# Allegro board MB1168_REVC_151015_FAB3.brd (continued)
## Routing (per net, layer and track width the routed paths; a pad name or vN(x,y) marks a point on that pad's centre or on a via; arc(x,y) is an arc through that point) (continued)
NETCN6_7: length 27.6
  TOP w0.127: U7.9 14.95,107.23 12.55,109.63 12.55,125.63 11.76,126.42 7.8,126.42 CN6.7
NETCN6_8: length 33.2
  TOP w0.127: U7.7 14.41,108.53 13,109.93 13,125.93 12.19,126.75 9.65,126.75 8.38,128.02 7.24,128.02 6.22,127 6.22,125.22 CN6.8
NETCN7_2: length 10.1
  TOP w0.127: U8.6 97.7,103.55 102.77,108.61 CN7.2
NETCN7_3: length 10.2
  TOP w0.127: U8.10 98.27,106.15 103.5,111.38 CN7.3
NETCN7_6: length 12.6
  TOP w0.127: U8.5 97.82,102.9 102.11,107.19 106.65,107.19 CN7.6
NETCN7_7: length 12.9
  TOP w0.127: U8.9 98.26,105.5 103,110.24 106.43,110.24 CN7.7
NETCN7_8: length 20
  TOP w0.127: CN7.8 108.46,110.97 108.46,109.22 107.82,108.58 106.05,108.58 104.78,109.86 103.25,109.86 97.59,104.2 U8.7
NETCN8_2: length 7.7
  TOP w0.127: R59.1 CN8.2 41.43,102.01 41.43,101.63 SB29.2
NETCN9_4: length 3.4
  TOP w0.127: R74.2 6.73,146.56 5.73,147.56 CN9.4
NETCN10_14: length 96.2
  TOP w0.127: R4.2 32.38,154.94 30.61,154.94 v1(30.35,154.69)
  BOTTOM w0.127: 41.94,88.77 41.94,95.54 45.59,99.19 45.59,104.01 46.86,105.28 46.86,113.92 50.61,117.67 51.75,117.67 54.36,120.27 54.36,131.32 55.12,132.08 57.02,132.08 57.53,132.59 57.53,136.4 52.32,141.6 47.75,141.6 44.32,145.03 35.94,145.03 30.48,150.5 30.48,154.56 v1(30.35,154.69)
NETCN11_2: length 18
  TOP w0.127: 108.01,78.87 105.03,78.87 104.78,79.12 102.25,79.12 U15.4 102.24,80.78 R100.1 102.36,82.17 101.85,82.68 101.85,84.45 101.22,85.09 99.06,85.09 98.04,84.07 CN11.2
NETCN11_4: length 20.3
  TOP w0.127: CN11.4 97.41,82.8 99.31,84.71 101.09,84.71 101.47,84.33 101.47,82.68 100.97,82.17 R99.2 100.94,80.88 U15.5 100.94,78.64 101.35,78.23 104.65,78.23 106.55,76.33 CN12.9
NETCN11_10: length 21.3
  TOP w0.127: CN12.15 102.87,68.71 R111.1 102.74,69.8 99.95,72.59 99.95,74.8 100.94,75.8 U15.1 100.94,77.75 99.69,78.99 CN11.10
NETCN12_11: length 6.5
  TOP w0.127: 108.01,73.79 103.12,73.79 R108.1 102.87,73.53 R109.2
NETCN12_17: length 5.3
  TOP w0.127: R113.2 102.87,66.17 CN12.17
NETCN12_19: length 5.3
  TOP w0.127: R115.2 102.87,63.63 108.01,63.63
NETCN13_2: length 31.5
  TOP w0.127: CN13.2 16.48,71.28 R110.1 17.4,69.34 17.91,68.83 19.3,68.83 22.03,66.1 22.03,64.2 22.73,63.5 37.47,63.5 R119.1 R120.2
NETCN13_7: length 89.9
  TOP w0.127: R144.1 88.77,51.44 84.71,47.37 51.05,47.37 49.78,48.64 32.26,48.64 26.04,54.86 26.04,61.85 25.53,62.36 22.1,62.36 20.32,64.14 18.16,64.14 R114.1 17.65,65.15 17.65,66.29 16,66.29 15.48,65.78 CN13.7
NETCN13_10: length 14.2
  TOP w0.127: R116.2 17.4,63.12 15.49,61.21 6.28,61.21 CN13.10
NETCN14_12: length 3.2
  TOP w0.127: R101.2 39.4,74.14 39.4,70.99
NETCN14_20: length 3.2
  TOP w0.127: R102.2 49.53,71.02 49.56,70.99
NETCN14_22: length 3.2
  TOP w0.127: 52.1,70.99 52.07,71.02 R103.2
NETCN14_24: length 53.5
  TOP w0.127: 54.64,70.99 56.04,69.6 62.87,69.6 63.63,70.36 63.63,75.18 66.67,78.23 80.52,78.23 88.14,85.85 88.14,92.74 R87.1
NETCN14_26: length 63.3
  TOP w0.127: 57.18,70.99 58.2,69.98 62.61,69.98 63.25,70.61 63.25,75.44 66.67,78.87 80.26,78.87 87.12,85.72 87.12,92.58 83.19,96.52 83.19,105.54 R62.1
NETCN14_30: length 58.1
  TOP w0.127: R61.1 82.68,106.55 82.68,96.27 86.61,92.33 86.61,85.94 80.05,79.38 66.55,79.38 62.26,75.09 62.26,70.99
NETCN14_32: length 41.4
  TOP w0.127: 64.8,70.99 64.8,75.72 66.8,77.72 81.03,77.72 88.65,85.34 88.65,91.85 R88.1
NETCN14_34: length 3.2
  TOP w0.127: R104.2 67.31,71.02 67.34,70.99
NETCN14_36: length 3.4
  TOP w0.127: R105.1 69.85,71.02 69.88,70.99
NETCN14_38: length 3.2
  TOP w0.127: R106.2 72.39,71.02 72.42,70.99
NETCN14_40: length 3.2
  TOP w0.127: R107.2 74.93,71.02 74.96,70.99
NETCN16_1: length 3.3
  TOP w0.127: CN16.1 93.85,56.52 R72.2
NETCN16_2: length 8.4
  TOP w0.127: CN16.2 95.89,54.74 95.89,52.96 95.12,52.2 93.6,52.2 93.09,52.7 R75.2
NETCN16_3: length 3.3
  TOP w0.127: CN16.3 93.85,53.98 R135.1
NETCN16_7: length 5
  TOP w0.127: R144.2 92.46,51.44 93.22,50.67 93.22,49.53 CN16.7
NETCN16_8: length 16.1
  TOP w0.508: CN16.8 95.89,47.12 92.58,47.12 91.82,46.35 R145.1 91.06,46.86 91.44,47.24 91.44,47.76 T11.1 ; T11.1 92.4,47.82 92.58,48.01 92.58,48.51 92.33,48.77 T11.2 T11.5 ; T11.1 T11.6
NETCN17_2: length 6.9
  TOP w0.155: CN17.2 102.81,25.9 102.81,25.62 101.41,24.22 101.41,21.4 R193.2
NETCN17_3: length 8.1
  TOP w0.155: CN17.3 103.19,25.9 103.19,25.46 101.79,24.07 101.79,21.4 R194.2 R195.2
NETCN18_1: length 10.5
  TOP w0.508: 20.81,22.64 U27.1 ; U27.1 22.1,23.12 ; U27.1 23.38,22.64 ; U27.1 22.1,22.16 ; CN18.1 11.84,19.3 ; CN18.1 10.64,21.59 ; CN18.1 10.64,17.02 ; CN18.1 9.45,19.3
NETCN19_4: length 3.7
  TOP w0.127: R192.1 72.14,20.01 CN19.4
NETD1_1: length 2.3
  TOP w0.127: D1.1 29.23,133.5 R35.1
NETD1_2: length 2.3
  TOP w0.127: JP3.2 D1.2
NETD2_1: length 2.3
  TOP w0.127: D2.1 JP6.2
NETD2_2: length 26
  TOP w0.127: U7.16 26.27,104.63 v1(26.29,104.65) R63.1 ; D2.2 29.21,125.08 v1(28.07,125.08)
  BOTTOM w0.127: v1(28.07,125.08) 27.18,124.19 27.18,115.32 25.4,113.54 25.4,109.22 26.92,107.7 26.92,105.28 v1(26.29,104.65)
NETD7_2: length 1.4
  TOP w0.127: D7.2 R168.2
NETJP1_3: length 33
  TOP w0.127: v1(61.72,110.11) 51.56,110.11 JP17.3 ; v1(61.72,113.03) 62.61,112.14 69.72,112.14 JP1.3 72.64,105.54 TP18.1
  BOTTOM w0.127: v1(61.72,110.11) v1(61.72,113.03)
NETJP2_1: length 2.5
  TOP w0.127: R29.2 JP2.1
NETJP5_2: length 5.2
  TOP w0.127: JP5.2 R40.1 TP6.1
NETJP8_1: length 4.1
  TOP w0.127: JP8.1 R59.2
NETJP8_2: length 19.5
  TOP w0.127: JP8.2 46.99,109.6 63.25,109.6 63.63,109.22
NETJP9_3: length 11.7
  TOP w0.127: U7.17 24.13,105.28 23.5,104.65 23.5,103.63 23.88,103.25 28.07,103.25 JP9.3
NETJP10_3: length 22.3
  TOP w0.356: U21.5 84.16,42.38 v1(84.71,42.93)
  TOP w0.508: 102.44,49.66 JP10.3 ; JP10.3 103.38,48.72 ; JP10.3 104.32,49.66 ; JP10.3 103.38,50.6 ; 83.77,52.7 R134.1 83.19,52.13
  TOP w0.762: R130.1 51.69,51.56 ; R133.1 75.95,50.04 ; R132.1 66.29,50.04 ; R131.1 58.93,49.91
  BOTTOM w0.508: v1(84.05,49.35) 84.05,44.98 84.71,44.32 v1(84.71,42.93)
NETJP11_4: length 15.3
  TOP w0.508: JP11.4 8.51,44.45 9.53,43.43 12.06,43.43 12.83,44.2 12.83,44.96 15.11,47.24 L5.1 17.66,47.24 19.56,45.34 SB38.2
NETJP12_2: length 3.7
  TOP w0.508: L6.1 103.63,41.02 JP12.2
NETL9_1: length 3.7
  TOP w0.508: L9.1 86.11,29.08 SB40.2
NETL12_1: length 3.2
  TOP w0.127: R142.1 R141.2 L12.1
NETLD1_2: length 3.2
  TOP w0.127: R202.2 LD1.2
NETLD2_2: length 3.2
  TOP w0.127: R201.2 LD2.2
NETLD3_2: length 3.2
  TOP w0.127: R200.2 LD3.2
NETLD4_2: length 3.2
  TOP w0.127: R199.2 LD4.2
NETLD5_1: length 1.5
  TOP w0.127: LD5.1 R153.1
NETLD6_2: length 1.8
  TOP w0.127: R204.2 52.69,13.58 LD6.2
NETLD6_3: length 1.9
  TOP w0.127: LD6.3 50.92,12.06 52.58,12.06 R209.2
NETLD6_4: length 2.2
  TOP w0.127: LD6.4 45.84,12.08 R208.1
NETLD7_2: length 5.3
  TOP w0.127: R210.1 LD7.2
NETLD8_1: length 32.8
  TOP w0.127: U28.1 28.79,25.61 27.94,24.77 26.08,24.77 25.02,23.71 25.02,21.55 22.86,19.39 22.86,17.4 19.94,14.48 16,14.48 14.61,13.08 14.61,12.32 15.37,11.56 15.37,5.46 LD8.1
NETLD8_2: length 5.3
  TOP w0.127: LD8.2 R211.1
NETLD9_1: length 31.1
  TOP w0.127: U28.7 28.14,23.93 27.81,24.26 26.29,24.26 25.53,23.5 25.53,21.34 23.37,19.18 23.37,17.27 20.07,13.97 16.89,13.97 16.38,13.46 16.38,12.32 17.27,11.43 17.27,5.33 LD9.1
NETLD9_2: length 5.3
  TOP w0.127: R212.1 LD9.2
NETLD10_1: length 70.4
  TOP w0.127: R65.2 45.59,41.15 46.35,41.91 46.35,45.34 47.62,46.61 49.28,46.61 49.78,46.1 74.8,46.1 75.44,45.47 87,45.47 89.03,43.43 89.03,38.1 93.09,34.04 100.33,34.04 LD10.1
NETLD10_2: length 75.3
  TOP w0.127: LD10.2 99.22,34.45 93.26,34.45 89.44,38.27 89.44,43.6 87.17,45.88 75.61,45.88 74.97,46.51 50.13,46.51 49.5,47.15 47.4,47.15 45.72,45.47 45.72,42.04 44.96,41.27 44.96,39.37 R68.2 44.45,38.73 43.48,39.71 U29.8
NETLS1_1: length 70.5
  TOP w0.127: R18.2 50.42,153.42 49.4,154.43 38.99,154.43 38.48,154.94 38.48,156.08 ; 37.97,165.61 37.97,166.12 38.35,166.5 86.74,166.5 87.25,165.99 87.25,165.35
NETLS1_2: length 13.1
  TOP w0.127: 54.86,156.46 54.86,154.18 55.63,153.42 59.44,153.42 60.33,152.53 R12.2
NETLS1_3: length 9.5
  TOP w0.127: 71.12,156.34 71.12,153.8 68.71,151.38 R13.2
NETR1_1: length 190.6
  TOP w0.127: R10.1 v1(34.29,149.86) 35.18,150.75 35.18,165.1 R1.1 ; R52.2 v1(74.93,116.08) R53.1 ; R177.1 75.06,30.1 74.3,30.1 v1(73.53,30.86)
  BOTTOM w0.127: v1(73.53,30.86) 73.28,30.86 70.23,33.91 70.23,43.14 75.1,48.01 77.22,48.01 84.58,55.37 84.58,63.45 83.57,64.47 83.57,80.64 87.5,84.58 87.5,90.04 82.8,94.74 82.8,107.31 76.83,113.28 75.31,113.28 74.42,114.17 74.42,115.19 74.93,115.7 v1(74.93,116.08) 74.93,116.59 73.15,118.36 68.93,118.36 67.82,119.48 67.82,133.1 64.9,136.02 61.72,136.02 58.42,139.32 56.13,139.32 49.53,145.92 37.08,145.92 34.29,148.72 v1(34.29,149.86)
NETR2_1: length 188.7
  TOP w0.127: R2.1 34.42,163.32 34.42,151.51 v1(34.29,151.38) R9.1 ; R55.2 v1(74.93,114.55) R56.1 ; R179.1 v1(75.06,28.57)
  BOTTOM w0.127: v1(34.29,151.38) 35.18,150.5 35.18,148.97 37.85,146.3 49.66,146.3 56.28,139.68 58.57,139.68 61.98,136.27 65.41,136.27 68.2,133.48 68.2,119.63 69.09,118.75 73.41,118.75 75.56,116.59 75.56,115.7 74.93,115.06 v1(74.93,114.55) 74.93,114.3 75.44,113.79 76.83,113.79 83.31,107.31 83.31,95 87.88,90.42 87.88,84.33 84.07,80.52 84.07,64.64 84.96,63.75 84.96,55.12 77.34,47.5 75.31,47.5 70.61,42.8 70.61,34.04 73.03,31.62 74.17,31.62 74.93,30.86 74.93,28.7 v1(75.06,28.57)
NETR4_1: length 4.6
  TOP w0.127: 31.62,154.18 31.88,153.92 R6.2 31.75,152.53 U2.3
NETR5_1: length 3.6
  TOP w0.127: R5.1 21.34,152.15 ; 21.72,151.76 22.23,151.26 U2.7
NETR9_2: length 2.8
  TOP w0.127: 31.62,151.38 31.5,151.26 U2.2
NETR10_2: length 2.8
  TOP w0.127: 31.62,149.86 31.5,149.99 U2.1
NETR12_1: length 2
  TOP w0.127: SB8.2 R12.1
NETR13_1: length 2
  TOP w0.127: SB11.1 68.7,146.3 R13.1
NETR18_1: length 1.7
  TOP w0.127: SB6.2 R18.1
NETR20_1: length 7.7
  TOP w0.127: R22.1 R21.1 R20.1 109.35,141.35 108.28,140.28 U4.3
NETR23_1: length 1.5
  TOP w0.127: R24.2 R23.1
NETR24_1: length 3.1
  TOP w0.127: U4.5 100.5,140.93 R24.1
NETR32_1: length 5.7
  TOP w0.127: R32.1 108.93,138.98 U4.1 105.7,138.98 105.16,138.43 R34.2
NETR32_2: length 4.2
  TOP w0.127: R33.1 R32.2 108.89,139.63 U4.2
NETR35_2: length 30.1
  TOP w0.127: R35.2 v1(27.18,133.48) ; U7.20 25.82,107.23 26.04,107.44 v1(26.29,107.44)
  BOTTOM w0.127: v1(26.29,107.44) 26.16,107.44 24.89,108.71 24.89,113.67 26.54,115.32 26.54,132.84 v1(27.18,133.48)
NETR36_2: length 4.7
  TOP w0.127: R36.2 32.77,130.94 SW1.2
NETR37_2: length 1.9
  TOP w0.127: R37.2 40.01,131.06 SB17.1
NETR57_1: length 3.7
  TOP w0.254: U6.5 32.64,112.65 R58.2 R57.1
NETR61_2: length 2.7
  TOP w0.127: U8.16 86.72,108.1 R61.2
NETR62_2: length 2.7
  TOP w0.127: U8.17 86.62,107.45 R62.2
NETR66_1: length 1.8
  TOP w0.127: U29.5 R66.1
NETR67_2: length 6.2
  TOP w0.127: R67.2 55.37,100.71 U9.3 U9.4
NETR83_1: length 3.5
  TOP w0.127: U12.2 92.82,95.63 92.18,96.27 R83.1 91.54,95.12 R87.2
NETR88_2: length 3.9
  TOP w0.127: R89.1 91.8,92.46 R88.2 92.51,94.18 92.51,94.89 92.74,95.13 U12.3
NETR90_2: length 2.2
  TOP w0.508: R90.2 6.71,89.69 U14.1
NETR91_1: length 2.4
  TOP w0.127: U14.5 5.24,85.89 R91.1
NETR93_1: length 3.8
  TOP w0.127: U13.2 18.17,83.44 R94.1 16.89,83.19 R93.1
NETR95_1: length 3.8
  TOP w0.127: R96.1 20.07,83.19 R95.1 18.66,83.57 U13.3
NETR101_1: length 20.9
  TOP w0.127: R117.1 35.56,60.83 v1(35.81,60.83) R118.1 36.18,59.68 U18.5 ; v1(38.35,75.69) R101.1
  BOTTOM w0.127: v1(35.81,60.83) 35.81,65.28 38.35,67.82 v1(38.35,75.69)
NETR116_1: length 71.2
  TOP w0.127: v1(20.32,63.37) R116.1 ; U25.15 61.88,32.48 61.59,32.77 58.04,32.77 v1(56.01,30.73)
  BOTTOM w0.127: v1(56.01,30.73) 55.5,30.23 48.39,30.23 47.37,31.24 47.37,35.43 49.78,37.85 49.78,44.2 41.4,52.58 35.69,52.58 34.8,53.47 34.16,53.47 32.56,55.07 32.56,56.46 32.08,56.95 30.68,56.95 28.96,58.67 26.54,58.67 25.65,59.56 23.37,59.56 20.32,62.61 v1(20.32,63.37)
NETR119_2: length 2.1
  TOP w0.127: R119.2 38.74,59.57 U19.7
NETR121_1: length 10.4
  TOP w0.127: R122.1 R121.1 43.18,60.83 43.18,59.44 39.75,56.01 38.99,56.01 38.74,55.75 U19.2
NETR129_1: length 4
  TOP w0.254: R129.1 R143.2 23.75,52.07 24.51,51.31 U20.5
NETR136_1: length 3
  TOP w0.127: R137.1 R136.1 30.74,53.97 U17.2
NETR138_1: length 1.7
  TOP w0.127: R138.1 35.18,54.61 U18.2
NETR139_1: length 3.1
  TOP w0.127: U19.3 39.24,54.11 R139.1 R140.2
NETR142_2: length 8.1
  TOP w0.127: R142.2 43.31,53.09 v1(43.18,53.09) ; U19.6 39.24,58.27 v1(39.24,57.15)
  BOTTOM w0.127: v1(43.18,53.09) 43.05,53.09 39.24,56.9 v1(39.24,57.15)
NETR147_1: length 2.2
  TOP w0.457: R147.1 23.56,45.78 U20.1
NETR149_1: length 4.6
  TOP w0.508: U22.5 98.42,41.27 R154.2 R149.1
NETR149_2: length 109.1
  TOP w0.127: R149.2 v1(99.95,44.96)
  BOTTOM w0.127: RV1.1 43.05,8.26 46.74,11.94 64.26,11.94 65.02,11.18 97.16,11.18 103.25,17.27 103.25,19.68 99.69,23.24 99.69,44.7 v1(99.95,44.96)
NETR157_1: length 4.7
  TOP w0.127: U25.2 69.56,35.9 69.98,36.32 69.98,37.21 69.6,37.59 R157.1 70.61,38.1 R158.2
NETR159_1: length 5.3
  TOP w0.356: U21.1 86.53,40.43 86.49,40.39 ; 86.49,40.39 R159.1 ; 86.49,40.39 86.49,40.77 86.8,41.08 U21.2
NETR159_2: length 4.4
  TOP w0.127: U23.5 84.29,35.27 84.96,35.94 R163.1 R159.2
NETR162_1: length 5.7
  TOP w0.356: R162.1 84.58,39.75 84.58,41.15 ; U21.7 84.51,41.08 84.58,41.15 ; 84.58,41.15 84.58,41.53 84.38,41.73 U21.6
NETR163_2: length 6.6
  TOP w0.127: 86.49,33.96 R163.2 ; 86.49,33.96 U23.2 ; 86.49,33.96 86.49,33.53 86.7,33.31 U23.1
NETR166_2: length 3.1
  TOP w0.127: U25.46 73.12,32.48 R166.2
NETR169_2: length 2.7
  TOP w0.127: R169.2 74.15,31.98 U25.45
NETR171_1: length 2.3
  TOP w0.127: R171.1 60.82,31.48 U25.17
NETR171_2: length 4.3
  TOP w0.127: U25.16 61.74,31.98 61.34,32.38 59.94,32.38 R171.2
NETR172_1: length 2.5
  TOP w0.127: R172.1 50.28,31.48 U24.20
NETR174_1: length 3.2
  TOP w0.127: U25.44 73.8,31.48 R174.1
NETR175_1: length 2.6
  TOP w0.127: R175.1 36.69,29.98 U24.44
NETR176_1: length 4.3
  TOP w0.127: U25.21 61.96,29.48 61.34,30.1 59.82,30.1 R176.1
NETR176_2: length 2.5
  TOP w0.127: U25.22 61.85,28.98 61.37,29.46 R176.2
NETR177_2: length 3.3
  TOP w0.127: U25.43 72.65,30.98 R177.2
NETR178_2: length 3.1
  TOP w0.127: U26.2 54.61,28.45 R178.2 R181.2
NETR179_2: length 4.3
  TOP w0.127: R179.2 73.66,28.45 73.66,29.34 72.51,30.48 U25.42
NETR180_1: length 5.2
  TOP w0.127: U25.41 72.38,29.98 73.41,28.96 73.41,27.18 R180.1
NETR182_2: length 3.9
  TOP w0.127: R182.2 39.5,24.33 39.9,24.74 40.67,24.74 41.18,25.26 U24.2
NETR183_2: length 2.9
  TOP w0.127: U24.3 41.68,24.79 R183.2
NETR187_1: length 6.9
  TOP w0.127: U24.12 46.18,25.93 46.48,25.63 47.45,25.63 48.56,24.51 49.33,24.51 49.89,23.95 49.89,23.01 R187.1
NETR188_1: length 4.6
  TOP w0.127: U25.28 66.06,24.79 65.41,24.13 65.41,22.99 R188.1
NETR188_2: length 2.8
  TOP w0.127: U25.27 65.56,24.67 R188.2
NETR189_1: length 4.3
  TOP w0.127: U25.30 67.06,23.12 R189.1
NETR189_2: length 2.6
  TOP w0.127: U25.29 66.56,24.14 R189.2
NETR190_1: length 4.5
  TOP w0.127: R190.1 68.45,22.99 68.45,24.38 68.06,24.78 U25.32
NETR190_2: length 2.6
  TOP w0.127: U25.31 67.56,24.13 R190.2
NETR191_1: length 10.9
  TOP w0.127: U25.26 65.06,25.56 64.01,24.51 64.01,21.72 64.26,21.46 68.45,21.46 R191.1
NETR191_2: length 2.8
  TOP w0.127: R191.2 68.56,24.66 U25.33
NETR195_1: length 2.5
  TOP w0.127: T14.2 103.5,17.63 R195.1
NETR196_1: length 11.8
  TOP w0.127: R196.1 R197.2 v1(27.56,18.29) ; v1(28.14,25.84) U28.2
  BOTTOM w0.127: v1(28.14,25.84) 28.14,19.88 27.56,19.3 v1(27.56,18.29)
NETR197_1: length 4.1
  TOP w0.127: U28.6 27.49,19.74 R197.1 R198.2
NETR205_2: length 4.3
  TOP w0.127: T14.1 103.5,15.39 R207.2 R206.1 R205.2
NETSB33_2: length 7.3
  TOP w0.127: SB33.2 55.37,102.36 U11.4 55.69,103.06 56.52,103.89 57.4,103.89 57.59,104.07 U11.1
NETTP26_1: length 10
  TOP w0.127: U25.11 65.06,35.78 64.64,36.2 61.21,36.2 60.71,35.69 57.91,35.69 TP26.1
NETTP27_1: length 7.5
  TOP w0.127: TP27.1 64.64,36.83 65.56,35.91 U25.10
NETTP28_1: length 6.6
  TOP w0.127: TP28.1 52.17,32.36 49.89,32.36 49.51,31.98 U24.21
NETTP29_1: length 8.5
  TOP w0.127: U25.12 57.94,35.08 TP29.1
NETTP31_1: length 23.3
  TOP w0.127: TP31.1 65.53,13.84 65.53,19.3 63.63,21.21 63.63,26.92 65.66,28.96 65.66,31.5 64.17,32.98 U25.14
NETU1_2: length 10.4
  TOP w0.127: U3.3 107.77,147.26 108.2,147.7 108.2,149.35 110.87,152.02 110.87,153.67 110.49,154.05 U1.2
NETU1_4: length 14.7
  TOP w0.127: U1.4 107.7,156.59 107.19,156.08 107.19,151.26 106.81,150.88 102.81,150.88 102.41,150.48 U3.5
NETU7_13: length 32.1
  TOP w0.279: U7.13 16.49,104.63 v1(16.26,104.39) ; U13.7 18.17,89.4 17.78,89.79 v1(17.14,89.79)
  TOP w0.508: v1(17.14,89.79) 10.03,89.79 8.51,88.27 5.84,88.27 5.36,87.78 U14.3
  BOTTOM w0.381: v1(17.14,89.79) 16.26,90.68 v1(16.26,104.39)
NETU8_13: length 15.6
  TOP w0.127: v1(94.36,108.08) 95.86,108.08 U8.13 ; U12.7 95.13,95.63 v1(94.87,95.89)
  BOTTOM w0.127: v1(94.36,108.08) 94.49,108.08 95,107.57 95,96.01 v1(94.87,95.89)
NETU24_13: length 2.5
  TOP w0.127: U26.7 49.38,28.45 48.91,27.98 U24.13
OSC_IN: length 11.4
  TOP w0.203: X3.2 40.64,18.29 42.62,20.27 42.62,23.04 C112.2 42.68,24.27 U24.5
OSC_OUT: length 11.3
  TOP w0.203: X3.1 45.15,18.35 43,20.5 43,23.06 C113.2 43.18,24 U24.6
PA0: length 50.8
  TOP w0.127: CN5.5 87.12,137.92 71.63,137.92 65.96,132.25 U5.23 ; R38.2 v1(106.68,133.22)
  BOTTOM w0.127: CN5.5 91.44,142.24 96.52,142.24 R38.2 v1(106.68,133.22)
PA1: length 14
  TOP w0.127: SB12.2 SB11.2 68.71,142.74 68.71,135.51 65.95,132.75 U5.24
PA2: length 12.9
  TOP w0.127: U5.25 65.82,133.25 67.18,134.62 67.18,142.49 SB10.2 SB9.2
PA4: length 39.6
  TOP w0.127: U5.29 61.65,137.72 v1(61.85,137.92) ; CN5.6 91.19,142.49 89.41,142.49 87.5,144.4 84.2,144.4 JP2.2
  BOTTOM w0.127: JP2.2 80.9,144.91 70.87,144.91 64.77,138.81 62.74,138.81 v1(61.85,137.92)
PA5: length 42.5
  TOP w0.127: v1(80.14,148.72) R8.2 ; U5.30 61.15,137.86 v1(61.09,137.92)
  BOTTOM w0.127: v1(61.09,137.92) 63.37,140.21 65.15,140.21 73.66,148.72 v1(80.14,148.72) 86.49,148.72 87.88,147.32 87.88,144.53 88.9,143.51 CN5.3
PA7: length 34
  TOP w0.127: v1(62.23,133.35) 61.72,132.84 60.96,132.84 60.15,133.65 U5.32
  BOTTOM w0.127: JP1.2 74.04,110.36 73.03,110.36 66.42,116.97 66.42,128.91 62.23,133.1 v1(62.23,133.35)
PA11: length 58
  TOP w0.155: R69.1 12.36,149.1 12.81,148.65 14.81,148.65 18.57,144.89 18.57,130.62 19.46,129.73 23.05,129.73 CN4.14 25.21,129.73 26.99,129.73 28.83,127.89 37.97,127.89 39.12,126.75 45.62,126.75 46.23,126.14 46.23,125.22 47.76,123.69 48.29,123.69 48.34,123.75 U5.70
PA12: length 58
  TOP w0.155: U5.71 48.34,123.25 48.29,123.31 47.6,123.31 45.85,125.06 45.85,125.98 45.46,126.36 38.96,126.36 37.82,127.51 28.67,127.51 26.83,129.35 25.21,129.35 CN4.16 23.05,129.35 19.3,129.35 18.19,130.46 18.19,144.74 14.65,148.27 12.81,148.27 12.36,147.83 R70.1
PA13: length 31.6
  TOP w0.127: U5.72 46.92,122.75 45.34,124.33 45.34,124.71 R45.2 44.07,124.71 38.61,124.71 37.67,123.77 27.99,123.77 25.02,126.74 23.12,126.74 CN4.15
PA14: length 33.7
  TOP w0.127: U5.76 51.15,118.71 50.04,117.6 45.72,117.6 R51.2 43.05,120.27 39.24,120.27 38.48,119.51 27.94,119.51 26.42,121.03 26.42,123.44 CN4.18
PB0: length 9.2
  TOP w0.127: U5.35 58.65,135.91 58.29,136.27 58.29,137.67 59.31,138.68 59.31,140.72 59.56,140.97 SB14.1 SB8.1
PB1: length 7.5
  TOP w0.127: 57.53,140.34 57.15,139.95 57.15,136.78 58.15,135.78 U5.36 ; SB13.1 57.91,142.37 58.04,142.49
PB2: length 52.4
  TOP w0.127: v1(55.63,141.73) 55.63,140.21 R27.1 56.39,137.03 57.65,135.77 U5.37
  BOTTOM w0.127: v1(55.63,141.73) 56.52,140.84 65.02,140.84 73.41,149.22 87,149.22 88.39,147.83 88.39,145.16 88.77,144.78 91.44,144.78 CN5.4
PB3: length 4.6
  TOP w0.127: 57.66,114.94 57.65,114.94 U5.89
PB4: length 15.1
  TOP w0.127: U5.90 58.15,116.86 61.09,113.92 61.09,112.9 62.23,111.76 64.77,111.76 66.17,110.36 66.17,109.22
PB6: length 37.9
  TOP w0.127: U5.92 59.15,116.49 62.99,112.65 70.48,112.65 R55.1 73.15,115.32 87.38,115.32 CN5.23
PB7: length 40.7
  TOP w0.127: CN5.22 91.44,119.38 89.92,119.38 87.38,116.84 73.15,116.84 R52.1 69.34,113.03 63.12,113.03 59.65,116.5 U5.93
PB12: length 13.5
  TOP w0.127: SB6.1 SB5.1 48.9,137.41 47.12,135.64 47.12,134.24 48.1,133.25 U5.51
PB13: length 6.9
  TOP w0.127: U5.52 47.37,132.75 46.39,133.73 SB15.1 SB16.1
PC0: length 31.6
  TOP w0.127: U5.15 63.26,128.25 v1(63.12,128.4) ; JP17.2 53.59,110.62 v1(63.44,110.62)
  BOTTOM w0.127: v1(63.44,110.62) 63.44,112.33 63.12,112.65 63.12,115.19 63.63,115.7 63.63,127.89 v1(63.12,128.4)
PC6: length 10.4
  TOP w0.127: 41.78,130.68 SB17.2 SB18.2 43.56,130.18 43.81,129.92 45.72,129.92 46.48,129.16 46.48,127.51 46.86,127.13 48.51,127.13 48.64,127.25 U5.63
PC7: length 6
  TOP w0.127: U5.64 48.52,126.75 48.51,126.75 46.74,126.75 45.72,127.76 SB24.2 45.09,129.03
PC13: length 193.9
  TOP w0.127: U5.7 65.86,124.25 68.71,121.41 68.71,121.03 68.83,120.9 72.01,120.9 v1(72.14,120.78) ; v1(85.47,10.41) 85.47,16.76 77.72,24.51 v1(77.72,30.48) ; R214.2 v1(72.9,9.53) ; v1(83.31,131.7) 83.69,131.7 R39.1
  BOTTOM w0.127: v1(85.47,10.41) 73.79,10.41 v1(72.9,9.53) ; v1(77.72,30.48) 77.72,33.91 77.22,34.42 74.93,34.42 72.9,36.45 72.9,40.39 87,54.48 87,56.01 97.28,66.29 97.28,92.71 97.79,93.22 97.79,95.5 97.16,96.14 97.16,98.42 97.92,99.19 97.92,109.22 95.25,111.89 95.25,124.21 93.6,125.86 93.6,131.32 92.71,132.21 83.82,132.21 v1(83.31,131.7) 81.41,129.79 75.44,129.79 74.8,129.16 74.8,123.44 v1(72.14,120.78)
PC14: length 10.1
  TOP w0.203: U5.8 66,124.75 69.09,121.67 SB27.1 69.72,121.67 70.51,122.45 72.24,122.45 R49.2
PC15: length 9.4
  TOP w0.203: R48.2 72.34,122.78 70.51,122.78 69.72,123.57 SB26.1 67.94,123.57 66.26,125.25 U5.9
PD0: length 129.2
  TOP w0.127: v1(18.92,69.34) 19.3,69.34 22.61,66.04 22.61,64.14 22.86,63.88 37.72,63.88 39.24,62.36 41.53,62.36 41.66,62.23 41.66,60.83 R121.2 R120.1 ; CN4.17 22.99,124.33 24.51,124.33 26.04,122.81 26.04,120.9 27.81,119.13 40.51,119.13 42.42,117.22 52.96,117.22 53.65,117.91 U5.81
  BOTTOM w0.127: v1(18.92,69.34) 18.8,69.47 18.8,86.74 19.43,87.38 19.43,103.76 18.03,105.16 18.03,123.95 19.81,125.73 CN4.17
PD1: length 176.4
  TOP w0.127: R200.1 58.17,23.11 v1(57.4,23.88) ; CN4.20 24.77,123.19 25.65,122.3 25.65,120.78 27.69,118.75 40.39,118.75 42.29,116.84 53.09,116.84 54.15,117.9 U5.82
  BOTTOM w0.127: v1(57.4,23.88) 57.4,25.02 53.85,28.57 50.42,28.57 49.15,29.84 48.26,29.84 46.99,31.11 46.99,35.56 49.4,37.97 49.4,44.07 41.27,52.2 35.31,52.2 34.54,52.96 34.16,52.96 31.5,55.63 31.5,56.36 31.24,56.62 30.45,56.62 28.91,58.17 24,58.17 19.56,62.61 19.56,69.85 19.18,70.23 19.18,80.14 19.81,80.77 19.81,81.53 19.3,82.04 19.3,85.09 19.81,85.6 19.81,104.01 18.41,105.41 18.41,122.68 20.07,124.33 22.99,124.33 CN4.20
PD3: length 60.6
  TOP w0.127: CN4.19 22.86,121.92 24.64,121.92 25.27,121.28 25.27,120.65 27.56,118.36 40.13,118.36 42.04,116.46 53.21,116.46 55.15,118.4 U5.84 ; v1(26.29,106.68) 26.59,106.68 R63.2
  BOTTOM w0.127: CN4.19 22.86,121.92 24.89,121.92 25.78,121.03 25.78,115.32 24.38,113.92 24.38,108.58 v1(26.29,106.68)
PD4: length 69.4
  TOP w0.127: v1(55.24,120.9) 55.27,120.9 55.65,120.52 U5.85 ; v1(37.72,80.26) 37.34,80.64 21.59,80.64 R96.2
  BOTTOM w0.127: v1(37.72,80.26) 38.1,80.26 43.18,85.34 43.18,92.96 48.77,98.55 48.77,102.36 47.62,103.5 47.62,113.67 50.8,116.84 51.94,116.84 55.24,120.14 v1(55.24,120.9)
PD5: length 85.5
  TOP w0.127: v1(19.81,79.88) 19.56,80.14 18.41,80.14 R93.2 ; CN4.22 24.77,120.65 27.43,117.98 39.88,117.98 41.78,116.08 53.47,116.08 56.15,118.76 U5.86
  BOTTOM w0.127: CN4.22 22.86,119.38 20.07,119.38 18.92,118.24 18.92,105.54 20.19,104.27 20.19,85.34 19.68,84.84 19.68,82.17 20.19,81.66 20.19,80.26 v1(19.81,79.88)
PD6: length 70.6
  TOP w0.127: JP9.2 29.97,102.62 23.5,102.62 22.73,103.38 22.73,112.65 20.45,114.94 20.45,119.51 CN4.21 22.48,119.76 25.02,119.76 27.18,117.6 39.75,117.6 41.66,115.7 53.59,115.7 56.65,118.75 U5.87
PD7: length 64.7
  TOP w0.254: 62.87,100.2 62.87,102.36 63.4,102.36 63.98,102.95 63.98,106.71 64.97,107.7 64.97,110.24 63.96,111.25 61.98,111.25 60.96,112.27 56.77,112.27 54.74,114.3 54.74,115.19
  TOP w0.279: U5.88 57.15,117.6 54.74,115.19 41.4,115.19 39.37,117.22 26.8,117.22 24.77,119.25 22.73,119.25 CN4.23
PE4: length 165.7
  TOP w0.127: U5.3 65.71,122.25 67.69,120.27 67.69,119.38 68.83,118.24 72.14,118.24 72.77,117.6 86.49,117.6 88.9,120.02 88.9,120.9 90.04,122.05 91.57,122.05 CN5.20 ; R202.1 63.25,19.3 61.47,21.08 v1(61.47,25.02)
  BOTTOM w0.127: v1(61.47,25.02) 61.47,25.91 62.48,26.92 74.8,26.92 76.33,28.45 76.33,32 72.14,36.2 72.14,40.77 86.11,54.74 86.11,56.52 96.14,66.55 96.14,109.6 94.49,111.25 94.49,121.41 CN5.20
PE5: length 164.7
  TOP w0.127: CN5.19 90.04,123.19 88.39,121.54 88.39,120.27 86.11,117.98 73.03,117.98 72.52,118.49 68.96,118.49 67.94,119.51 67.94,120.52 65.71,122.75 U5.4 ; R201.1 60.71,24.77 v1(60.45,25.02)
  BOTTOM w0.127: CN5.19 91.69,121.67 93.22,121.67 94.11,120.78 94.11,111.09 95.76,109.44 95.76,66.67 85.72,56.64 85.72,54.86 71.75,40.89 71.75,36.04 75.95,31.85 75.95,28.7 74.55,27.3 62.33,27.3 60.58,25.56 60.58,25.15 v1(60.45,25.02)
PE6: length 142.1
  TOP w0.127: U5.5 65.72,123.25 68.2,120.78 68.2,119.76 69.22,118.75 73.03,118.75 73.41,118.36 85.85,118.36 88.01,120.52 88.01,122.43 90.04,124.46 91.44,124.46 CN5.18 ; R166.1 v1(76.83,33.66)
  BOTTOM w0.127: v1(76.83,33.66) 75.18,33.66 72.52,36.32 72.52,40.51 86.49,54.48 86.49,56.13 96.52,66.17 96.52,109.86 94.87,111.51 94.87,123.83 92.96,125.73 CN5.18
PE7: length 209.9
  TOP w0.127: R199.1 55.63,23.62 v1(55.37,23.88) ; U5.38 57.15,133.22 v1(56.64,132.72)
  BOTTOM w0.127: v1(56.64,132.72) 57.15,133.22 57.15,136.4 52.32,141.22 47.5,141.22 44.07,144.65 22.73,144.65 CN4.3 19.43,143.51 14.86,138.94 14.86,112.52 13.72,111.38 13.72,90.93 16.13,88.52 16.13,61.72 22.99,54.86 29.21,54.86 31.11,52.96 31.11,50.16 32.38,48.9 42.8,48.9 48.26,43.43 48.26,38.61 44.07,34.42 44.07,29.69 49,24.77 54.48,24.77 v1(55.37,23.88)
PE8: length 197.7
  TOP w0.127: v1(56.65,133.6) U5.39 ; v1(53.98,26.16) 53.98,26.04 R181.1
  BOTTOM w0.127: v1(56.65,133.6) 56.65,133.73 56.77,133.85 56.77,136.27 54.48,138.56 49.28,138.56 44.32,143.51 CN4.4 23.24,143.51 22.1,142.37 19.05,142.37 15.37,138.68 15.37,112.39 14.1,111.12 14.1,91.06 16.51,88.65 16.51,61.98 23.24,55.24 29.21,55.24 31.37,53.09 31.37,50.42 32.38,49.4 42.8,49.4 48.64,43.56 48.64,38.35 44.45,34.16 44.45,29.84 47.62,26.67 53.47,26.67 v1(53.98,26.16)
PE9: length 193.2
  TOP w0.127: v1(55.5,132.72) 55.52,132.72 56.15,133.35 U5.40 ; R187.2 50.52,23.9 50.52,24.56 48.77,26.31 v1(48.77,27.18)
  BOTTOM w0.127: v1(55.5,132.72) 55.52,132.72 56.13,133.33 56.13,136.4 54.36,138.18 49.15,138.18 45.09,142.24 22.86,142.24 CN4.5 19.43,140.97 15.88,137.41 15.88,111.76 15.24,111.12 15.24,90.42 16.89,88.77 16.89,62.1 23.37,55.63 29.21,55.63 31.75,53.09 31.75,50.55 32.38,49.91 42.93,49.91 48.97,43.87 48.97,38.05 44.83,33.91 44.83,30.1 47.75,27.18 v1(48.77,27.18)
PE10: length 155.6
  TOP w0.127: U5.41 55.65,133.76 v1(55.5,133.6) ; R141.1 R140.1 41.02,51.69 v1(40.39,51.05)
  BOTTOM w0.127: v1(40.39,51.05) 39.75,50.42 32.51,50.42 32.13,50.8 32.13,53.09 29.21,56.01 23.75,56.01 17.27,62.48 17.27,88.9 15.62,90.55 15.62,111 16.26,111.63 16.26,136.27 19.68,139.7 21.97,139.7 23.24,140.97 CN4.6 24.89,141.73 44.96,141.73 49.02,137.67 54.36,137.67 55.63,136.4 55.63,133.73 v1(55.5,133.6)
PE11: length 40.7
  TOP w0.127: U5.42 55.15,136.11 v1(54.74,136.53) 54.74,139.32 R26.1
  BOTTOM w0.127: v1(54.74,136.53) 54.1,137.16 48.9,137.16 45.09,140.97 26.16,140.97 25.02,139.83 22.99,139.83 CN4.7
PE12: length 37
  TOP w0.127: U5.43 54.65,135.85 53.98,136.53 v1(53.72,136.53) 53.34,136.91 R25.1
  BOTTOM w0.127: CN4.8 25.02,138.43 26.8,140.21 45.34,140.21 49.02,136.53 v1(53.72,136.53)
PE13: length 136.1
  TOP w0.127: U5.44 54.15,133.68 v1(54.23,133.6) ; v1(32.64,51.18) 32.38,51.44 R137.2
  BOTTOM w0.127: v1(32.64,51.18) 32.64,53.09 29.34,56.39 24,56.39 17.65,62.74 17.65,90.3 16.89,91.06 16.89,131.83 20.95,135.89 CN4.9 22.73,137.03 25.27,137.03 27.69,139.45 45.47,139.45 49.28,135.64 52.58,135.64 54.15,134.06 54.15,133.68 v1(54.23,133.6)
PE14: length 112.4
  TOP w0.127: v1(54.23,132.72) 53.72,133.22 53.72,134.24 53.65,134.31 U5.45 ; R114.2 18.29,65.53 v1(18.16,65.53)
  BOTTOM w0.127: v1(54.23,132.72) 53.72,133.22 53.72,133.86 52.45,135.13 49.15,135.13 45.59,138.68 28.19,138.68 25.4,135.89 CN4.10 23.5,135.89 22.23,134.62 20.83,134.62 17.27,131.06 17.27,91.57 18.03,90.81 18.03,65.66 v1(18.16,65.53)
PE15: length 131.8
  TOP w0.127: v1(53.21,133.6) 53.15,133.67 U5.46 ; R138.2 v1(35.18,51.56)
  BOTTOM w0.127: v1(53.21,133.6) 53.15,133.67 53.15,133.73 52.26,134.62 49.02,134.62 45.72,137.92 28.83,137.92 25.65,134.75 23.11,134.75 22.61,134.24 22.61,131.83 CN4.13 17.65,126.87 17.65,92.08 18.41,91.31 18.41,67.94 19.05,67.31 19.05,61.98 23.24,57.78 28.57,57.78 30.99,55.37 31.11,55.37 34.04,52.45 34.29,52.45 v1(35.18,51.56)
PH0: length 14.2
  TOP w0.203: U5.12 69.33,126.75 69.34,126.75 ; X1.2 78.49,127.76 73.91,127.76 C27.1 72.9,127.25 72.59,127.56 70.28,127.56 69.85,127.13
PH1: length 8.1
  TOP w0.203: R42.1 72.26,129.67 71.88,129.29 70.61,129.29 70,128.68 ; U5.13 68.33,127.25 69.22,128.14
PH9: length 156.8
  TOP w0.127: v1(39.5,64.39) 84.71,64.39 v1(85.09,64.77) ; U5.10 67.92,125.75 68.58,125.09 R46.2 70.1,124.59 70.48,124.59 70.61,124.46 v1(72.14,124.46) ; R118.2 v1(36.58,62.74)
  BOTTOM w0.127: CN5.10 91.57,137.03 84.84,137.03 81.53,133.73 77.09,133.73 73.41,130.05 73.41,125.73 v1(72.14,124.46) 71.88,124.46 71.37,123.95 71.37,120.4 71.75,120.02 73.41,120.02 76.96,116.46 76.96,114.94 85.6,106.3 85.6,93.98 88.65,90.93 88.65,83.82 87.12,82.3 87.12,66.8 v1(85.09,64.77) ; v1(39.5,64.39) 38.23,64.39 v1(36.58,62.74)
PH10: length 147.5
  TOP w0.127: v1(73.41,40.01) 71.5,40.01 R158.1 ; v1(73.79,124.33) R47.2 72.39,125.73 68.71,125.73 68.18,126.25 U5.11
  BOTTOM w0.127: v1(73.41,40.01) 73.41,40.39 87.5,54.48 87.5,56.01 97.92,66.42 97.92,92.08 98.3,92.46 98.3,109.47 95.63,112.14 95.63,124.33 93.98,125.98 93.98,133.73 92.96,134.75 92.2,134.75 91.06,135.89 CN5.9 84.2,135.89 81.66,133.35 77.22,133.35 73.79,129.92 v1(73.79,124.33)
PWR_ENN: length 21.4
  TOP w0.127: U29.3 49.4,43.94 50.04,44.58 51.44,44.58 51.94,44.07 R71.1 53.09,43.18 53.85,42.42 53.85,39.5 52.07,37.72 46.1,37.72 44.68,36.3 U24.28
PWR_EXT: length 25.5
  TOP w0.127: v1(37.34,31.24) R173.2 R168.1 36.6,32.48 U24.39
  BOTTOM w0.127: v1(37.34,31.24) 37.21,31.24 36.07,30.1 36.07,24.89 33.35,22.17 33.35,13 JP13.2
RESET#: length 261
  TOP w0.127: v1(52.96,124.59) 53.34,124.21 62.61,124.21 63.63,125.22 63.63,127.38 64,127.75 U5.14 66.16,127.75 68.07,129.67 71.75,129.67 72.01,129.92 72.01,130.43 72.26,130.68 75.95,130.68 76.33,130.3 83.06,130.3 v1(83.19,130.43) 83.44,130.68 R41.1 ; 55.12,30.48 47.79,30.48 U24.18 ; 55.12,30.48 55.12,38.48 59.94,43.31 66.17,43.31 66.99,42.48 67.61,42.48 D8.2 69.07,42.04 v1(72.01,42.04) ; 55.12,30.48 55.88,29.72 55.88,25.27 54.48,23.88 54.48,11.94 53.72,11.18 R213.1 53.98,9.27 53.98,8.13 53.47,8.64 53.21,8.64 51.88,9.97 B1.3 B1.2 ; v1(92.84,68.96) 101.6,68.96 R111.2 ; v1(76.96,46.86) 85.09,46.86 87.94,49.72 T11.4
  BOTTOM w0.127: JP6.1 38.23,127 38.23,128.65 41.66,132.08 46.86,132.08 48.77,130.18 48.77,125.73 50.55,123.95 52.32,123.95 v1(52.96,124.59) ; v1(83.19,130.43) 83.44,130.68 86.11,130.68 88.14,128.65 88.14,115.19 93.73,109.6 93.73,106.93 94.23,106.43 94.23,87.5 92.84,86.11 v1(92.84,68.96) 92.84,64.39 85.34,56.9 85.34,54.99 77.22,46.86 v1(76.96,46.86) 75.82,46.86 72.01,43.05 v1(72.01,42.04)
SH0: length 36.6
  TOP w0.127: U25.4 68.56,36.17 v1(68.58,36.2) ; v1(77.34,56.01) 77.6,56.26 T9.4 ; R126.1 v1(82.3,56.01) 81.15,56.01 T10.3
  BOTTOM w0.127: v1(77.34,56.01) v1(82.3,56.01) 82.3,53.72 77.6,49.02 75.31,49.02 69.09,42.8 69.09,36.7 v1(68.58,36.2)
SH0_D: length 18.6
  TOP w0.508: R134.2 83.19,54.8 ; R134.2 82.6,54.23 ; R134.2 83.77,54.23 ; 79.53,54.99 T10.5 77.83,54.99 ; 79.53,54.04 T10.6 77.83,54.04 ; T9.5 77.6,53.43 ; T9.5 78.05,52.37 ; T9.5 77.6,51.3 ; T9.5 77.14,52.37 ; 80.23,54.04 T10.1 81.93,54.04 ; 80.14,51.3 T9.7 ; T9.7 80.14,53.43 ; T9.7 79.68,52.37 ; T9.7 80.59,52.37 ; 78.41,52.37 78.87,52.37 ; 78.87,52.37 79.32,52.37 ; 78.87,52.37 78.87,51.3 ; 80.95,52.37 T9.8 ; T9.8 81.41,51.3 ; T9.8 81.86,52.37 ; 80.23,54.99 T10.2 81.93,54.99
SH1: length 33.7
  TOP w0.127: T3.4 53.47,56.26 v1(53.21,56.01) ; v1(67.44,37.21) 68.06,36.59 U25.5 ; T4.3 57.02,56.01 v1(58.17,56.01) R123.1
  BOTTOM w0.127: v1(53.21,56.01) v1(58.17,56.01) 59.82,54.36 59.82,49.28 66.32,42.77 66.32,38.33 v1(67.44,37.21)
SH1_D: length 18.6
  TOP w0.508: 53.01,52.37 T3.5 ; T3.5 53.47,53.43 ; T3.5 53.92,52.37 ; T3.5 53.47,51.3 ; 57.8,54.99 T4.2 56.1,54.99 ; 57.28,51.3 T3.8 ; T3.8 57.73,52.37 ; T3.8 56.82,52.37 ; 55.4,54.04 T4.6 53.7,54.04 ; T3.6 55.19,52.37 ; T3.6 54.28,52.37 ; T3.6 54.74,51.3 ; T3.7 56.46,52.37 ; T3.7 56.01,53.43 ; T3.7 55.55,52.37 ; T3.7 56.01,51.3 ; 58.34,54.23 R131.2 ; R131.2 58.93,54.8 ; R131.2 59.51,54.23 ; 55.4,54.99 T4.5 53.7,54.99 ; 56.1,54.04 T4.1 57.8,54.04
SH2: length 37.6
  TOP w0.127: v1(67.44,36.19) 67.56,36.07 U25.6 ; T1.4 46.1,56.26 v1(45.85,56.01) ; R127.1 v1(50.8,55.88) 50.74,55.94 T2.3
  BOTTOM w0.127: v1(67.44,36.19) 65.81,37.82 65.81,42.52 54.1,54.23 52.45,54.23 v1(50.8,55.88) 45.97,55.88 v1(45.85,56.01)
SH2_D: length 18.6
  TOP w0.508: 51.1,54.23 R130.2 ; R130.2 52.27,54.23 ; R130.2 51.69,54.8 ; 47.37,51.3 T1.6 ; T1.6 47.83,52.37 ; T1.6 46.91,52.37 ; T1.7 49.1,52.37 ; T1.7 48.64,51.3 ; T1.7 48.64,53.43 ; T1.7 48.18,52.37 ; 46.34,54.04 T2.6 48.04,54.04 ; 48.74,54.04 T2.1 50.44,54.04 ; 48.74,54.99 T2.2 50.44,54.99 ; T1.5 46.56,52.37 ; T1.5 46.1,51.3 ; T1.5 45.64,52.37 ; T1.5 46.1,53.43 ; 49.91,51.3 T1.8 ; T1.8 50.37,52.37 ; T1.8 49.45,52.37 ; 48.04,54.99 T2.5 46.34,54.99
SH3: length 39.4
  TOP w0.127: v1(70.23,28.7) 70.45,28.48 U25.38 ; T6.3 64.38,56.01 v1(65.53,56.01) R124.1 ; T5.4 60.83,56.26 v1(60.58,56.01)
  BOTTOM w0.127: v1(70.23,28.7) 68.07,30.86 68.07,43.36 66.8,44.63 66.8,54.74 v1(65.53,56.01) v1(60.58,56.01)
SH3_D: length 18.6
  TOP w0.508: 60.83,51.3 T5.5 ; T5.5 60.38,52.37 ; T5.5 61.29,52.37 ; T5.5 60.83,53.43 ; T5.6 62.56,52.37 ; T5.6 61.65,52.37 ; T5.6 62.1,51.3 ; T5.7 63.37,53.43 ; T5.7 63.37,51.3 ; T5.7 62.92,52.37 ; T5.7 63.83,52.37 ; 64.64,51.3 T5.8 ; T5.8 65.1,52.37 ; T5.8 64.19,52.37 ; 61.07,54.04 T6.6 62.77,54.04 ; 65.17,54.99 T6.2 63.47,54.99 ; R132.2 66.29,54.8 ; R132.2 65.71,54.23 ; R132.2 66.88,54.23 ; 61.07,54.99 T6.5 62.77,54.99 ; 63.47,54.04 T6.1 65.17,54.04
SPI1_MOSI_3V3: length 7.4
  TOP w0.127: L11.1 32.51,62.36 32.89,62.74 34.29,62.74 34.54,62.48 34.54,59.82 35.18,59.18 U18.7
SPI1_SCK_3V3: length 2.9
  TOP w0.127: L4.1 29.72,56.52 30.74,57.54 U17.7
STL_USB_DM: length 76.5
  TOP w0.155: v1(101.22,18.9) 101.41,19.09 101.41,19.49 R193.1 ; v1(42.82,36.7) 42.62,36.51 42.62,35.73 42.68,35.68 U24.32
  BOTTOM w0.155: v1(42.82,36.7) 42.62,36.51 42.62,28.06 47.65,23.04 48.23,23.04 48.41,23.22 48.72,23.22 48.9,23.04 49.21,23.04 49.38,23.22 49.69,23.22 49.87,23.04 50.18,23.04 50.36,23.22 50.67,23.22 50.85,23.04 51.16,23.04 51.33,23.22 51.64,23.22 51.82,23.04 80.87,23.04 85.75,18.16 95.88,18.16 96.06,18.34 96.37,18.34 96.55,18.16 96.86,18.16 97.03,18.34 97.34,18.34 97.52,18.16 97.83,18.16 98.01,18.34 98.32,18.34 98.5,18.16 98.81,18.16 98.98,18.34 99.29,18.34 99.47,18.16 101.19,18.16 101.41,18.38 101.41,18.71 v1(101.22,18.9)
STL_USB_DP: length 76.6
  TOP w0.155: R194.1 101.79,19.49 101.79,19.09 v1(101.98,18.9) ; U24.33 42.18,35.71 42.24,35.77 42.24,36.51 v1(42.05,36.7)
  BOTTOM w0.155: v1(42.05,36.7) 42.24,36.51 42.24,27.91 47.49,22.66 80.72,22.66 85.59,17.78 101.35,17.78 101.79,18.22 101.79,18.71 v1(101.98,18.9)
STM_JTCK_SWCLK: length 11.7
  TOP w0.127: CN15.3 35.13,40.64 36.96,40.64 37.72,39.88 37.72,34.42 38.65,33.48 U24.37
STM_JTMS_SWDIO: length 11.9
  TOP w0.127: U24.34 41.68,35.08 41.68,34.32 41.27,33.91 40.01,33.91 38.23,35.69 38.23,40.08 CN15.1
STM_RST: length 4.3
  TOP w0.203: U24.7 43.68,24.64 C114.2 R184.1
T_JTCK: length 200.1
  TOP w0.127: v1(75.18,41.27) 73.28,43.18 67.06,43.18 66.42,43.81 59.82,43.81 52.32,36.32 v1(50.16,36.32) 46.23,36.32 45.68,35.78 U24.26 45.68,34.04 45.85,33.87 45.85,33.27 46.35,32.77 46.35,29.72 47.09,28.98 U24.15 ; R51.1 v1(42.29,118.49) ; R97.2 v1(100.97,83.95)
  BOTTOM w0.127: v1(42.29,118.49) 42.29,117.47 38.35,113.54 38.35,110.49 35.05,107.19 35.05,103.02 31.01,98.98 31.01,96.95 25.02,90.96 25.02,66.55 27.56,64.01 27.81,64.01 33.53,58.29 33.53,56.64 35.94,54.23 38.35,54.23 39.24,53.34 41.66,53.34 50.55,44.45 50.55,36.7 v1(50.16,36.32) ; v1(100.97,83.95) 100.97,78.99 99.06,77.09 99.06,66.8 88.01,55.75 88.01,54.51 75.18,41.69 v1(75.18,41.27)
T_JTMS: length 217.6
  TOP w0.127: R98.2 v1(102.36,83.95) ; v1(52.2,27.94) 52.2,28.37 52.78,28.95 U26.3 ; R45.1 v1(42.29,125.35) ; v1(45.34,33.53) 45.18,33.68 U24.27 45.18,35.91 46.1,36.83 v1(49.53,36.83) 52.2,36.83 59.56,44.2 66.67,44.2 67.24,43.63 74.48,43.63 v1(76.2,41.91)
  BOTTOM w0.127: v1(52.2,27.94) 47.75,27.94 45.34,30.35 v1(45.34,33.53) ; v1(76.2,41.91) 76.2,42.16 83.56,49.52 83.56,49.56 83.85,49.85 83.88,49.85 88.52,54.48 88.52,55.5 99.57,66.55 99.57,76.96 102.36,79.76 v1(102.36,83.95) ; v1(42.29,125.35) 41.91,125.35 40.39,123.83 40.39,117.09 37.21,113.92 37.21,110.87 35.94,109.6 34.8,109.6 32.26,107.06 32.26,103.73 30.59,102.07 30.59,100.19 28.7,98.3 28.7,96.52 23.88,91.69 23.88,66.04 24.26,65.66 24.26,64.26 25.27,63.25 27.94,63.25 33.12,58.06 33.12,56.41 36.58,52.96 41.53,52.96 50.16,44.32 50.16,37.47 v1(49.53,36.83)
T_SWDIO_IN: length 8.9
  TOP w0.127: v1(46.35,33.81) 46.18,33.98 U24.25 ; U26.6 v1(49.15,28.95)
  BOTTOM w0.127: v1(46.35,33.81) 46.35,30.63 48.04,28.95 v1(49.15,28.95)
TS_SHIELD: length 1
  TOP w0.127: R37.1 v1(40.01,135)
  vias: v1(37.59,153.16) v1(43.43,148.72) v1(48.77,153.03) v1(51.82,154.81) v1(52.07,148.46) v1(58.93,154.81) v1(58.93,152.27) v1(61.34,149.22) v1(68.07,149.22) v1(70.1,154.94) v1(71.12,149.35) v1(73.28,155.07) v1(85.98,154.94)
U5V: length 116.9
  TOP w0.279: U10.5 v1(6.35,148.46)
  TOP w0.381: C49.1 5.59,150.11 4.98,149.51 CN9.1
  TOP w0.508: 33.27,108.79 C44.1 ; C44.1 34.09,109.73 ; C44.1 32.46,109.73 ; C44.1 33.27,110.67 ; 34.12,111.29 U6.6 33.59,111.7 ; JP11.6 7.24,46.35 7.24,49.15 5.99,50.39 v1(5.99,52.96) D4.1 ; C49.1 v1(7.24,150.88)
  BOTTOM w0.508: v1(5.99,52.96) 7.24,54.2 7.24,57 10.82,60.58 12.95,60.58 14.88,62.51 14.88,88.67 13,90.55 13,143.88 v1(12.78,144.1)
  vias: v1(11.89,144.99) v1(11.89,144.1) v1(12.78,144.99) v1(32.13,110.62) v1(32.13,109.6) v1(32.13,108.84)
U5V_STLINK: length 33.2
  TOP w0.508: 42.41,43.94 U29.6 ; U29.6 44.54,43.94 ; U29.6 43.48,43.48 ; U29.6 43.48,44.4 ; L5.2 19.69,43.44 19.94,43.69 v1(21.21,43.69) ; C54.2 41.66,44.15 ; C54.2 42.11,43.69 ; C54.2 41.2,43.69 ; U29.7 44.54,42.67 ; U29.7 43.48,42.21 ; U29.7 43.48,43.13 ; U29.7 42.41,42.67
  BOTTOM w0.508: v1(40.74,44.25) 39.45,44.25 38.35,45.34 22.86,45.34 v1(21.21,43.69)
  vias: v1(40.74,43.51)
USART2_RTS_3V3: length 16.4
  TOP w0.127: U7.14 18.41,103.98 18.92,103.47 v1(18.92,103.38) ; U13.6 18.66,90.29 v1(18.92,90.55)
  BOTTOM w0.127: v1(18.92,103.38) v1(18.92,90.55)
USB_RENUMN: length 97.5
  TOP w0.127: U24.38 37.63,32.98 v1(37.47,33.15) ; v1(97.92,12.83) R205.1
  BOTTOM w0.127: v1(97.92,12.83) 96.65,11.56 65.15,11.56 64.41,12.29 46.56,12.29 42.93,8.66 34.65,8.66 32.97,10.34 32.97,22.43 35.69,25.15 35.69,31.5 37.34,33.15 v1(37.47,33.15)
USB_VBUS3V3: length 17.1
  TOP w0.508: 31.55,113.67 R58.1 ; R58.1 32.72,113.67 ; R58.1 32.13,114.24 ; 30.17,121.03 JP7.3 ; JP7.3 32.06,121.03 ; JP7.3 31.11,120.09 ; JP7.3 31.11,121.97 ; 29.08,120.5 C32.1 ; C32.1 28.63,120.95 ; C32.1 29.54,120.95 ; 31.88,114.63 TP9.1 ; TP9.1 30.94,115.57 ; TP9.1 31.88,116.51 ; TP9.1 32.82,115.57 ; 34.12,114.01 U6.4 33.59,113.6 ; 34.04,115.37 C36.1 ; C36.1 34.04,116.54 ; C36.1 33.41,115.95
  BOTTOM w0.508: 31.88,114.63 TP9.1 ; TP9.1 31.88,116.51 ; TP9.1 32.82,115.57 ; TP9.1 30.94,115.57
  vias: v1(28.55,120.02) v1(29.44,120.09) v1(30.23,115.32) v1(30.86,116.46)
VLCD: length 31.8
  TOP w0.127: U5.6 65.73,123.75 68.45,121.03 68.45,120.9 69.22,120.14 R50.1 70.87,119 73.66,119 73.91,118.75 85.6,118.75 87.63,120.78 87.63,123.19 CN5.17
VREF+: length 8.2
  TOP w0.279: 67.69,131.7 67.25,131.25 U5.21
  TOP w0.508: R40.2 71.37,131.57 C24.1 70.99,131.95 C23.2 67.94,131.95 67.69,131.7
VUSB_STLINK: length 143.7
  TOP w0.508: 46.61,39.19 R68.1 47.07,38.73 ; v1(79.12,28.07) 79.5,28.07 81.92,30.48 92.2,30.48 93.73,32 99.19,32 CN17.1 ; 51.49,42.16 R71.2 ; R71.2 52.4,42.16 ; R71.2 51.94,41.71 ; v1(12.95,51.44) 12.25,51.44 10.31,53.37 D6.1 ; 50.67,41.71 C48.1 ; C48.1 51.13,42.16 ; C48.1 50.22,42.16 ; U29.2 49.79,42.67 ; U29.2 48.72,42.21 ; U29.2 47.66,42.67 ; 46.61,39.42 R65.1 47.07,39.88 ; U29.1 49.79,41.4 ; U29.1 48.72,41.86 ; U29.1 48.72,40.94 ; U29.1 47.66,41.4 ; R207.1 v1(104.52,12.83)
  BOTTOM w0.508: v1(79.12,28.07) 76.83,28.07 75.06,26.29 64.9,26.29 62.87,24.26 59.56,24.26 57.02,26.8 57.02,31.11 54.99,33.15 54.99,35.69 52.83,37.85 v1(52.83,41.27) v1(52.83,42.04) ; v1(104.52,12.83) 104.52,19.81 100.58,23.75 100.58,27.69 101.98,29.08 CN17.1 ; v1(12.95,51.44) 18.8,51.44 19.56,52.2 25.65,52.2 29.84,48.01 41.53,48.01 47.37,42.16 v1(47.37,39.24)

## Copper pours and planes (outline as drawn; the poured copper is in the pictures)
+3V3 on TOP (solid shape): 88.14,26.67 86.77,26.67 87.28,27.18 86.77,27.69 88.14,27.69
+3V3 on TOP: 27.05,53.47 29.72,50.8 29.72,49.91 29.46,49.66 26.67,49.66 26.04,50.29 25.4,50.29 25.27,50.42 25.27,51.31 24.64,51.94 24.64,53.34 24.77,53.47
+3V3 on L2_VCC: outline of 88 points within 0.51,0.51 113.79,153.92
+3V3_STLINK on TOP: 21.84,61.98 25.27,61.98 25.53,61.72 25.53,59.94 25.4,59.82 21.72,59.82 21.59,59.94 21.59,61.72
+3V3_STLINK on L2_VCC: 38.33,21.34 35.94,23.73 35.94,32.87 35.28,33.53 33.38,33.53 20.83,46.08 20.83,61.62 21.19,61.98 25.68,61.98 25.91,61.74 25.91,49.17 26.82,48.26 50.82,48.26 51.94,47.14 51.94,33.25 49.66,30.97 49.66,28.98 50.93,27.71 50.93,24.74 47.52,21.34
+5V on TOP (solid shape): 88.14,28.58 86.77,28.58 87.28,29.08 86.77,29.59 88.14,29.59
+5V on TOP: 23.75,51.31 23.75,50.42 23.62,50.29 22.99,50.29 22.48,49.78 19.81,49.78 19.05,49.02 17.02,49.02 16.89,49.15 16.89,51.56 17.02,51.69 18.67,51.69 19.43,52.45 22.61,52.45
+5V on TOP: 97.41,42.29 97.03,41.91 96.01,41.91 95.89,42.04 95.89,42.93 95.25,43.56 95.25,46.48 95.38,46.61 97.28,46.61 97.41,46.48
+5V on L2_VCC: 26.27,7.62 14.61,19.28 14.61,47.65 17,50.04 20.32,50.04 20.32,45.87 33.17,33.02 35.07,33.02 35.43,32.66 35.43,30.1 26.44,30.1 25.27,28.93 25.27,21.87 26.18,20.95 29.36,20.95 37.11,13.21 69.19,13.21 83.06,27.07 83.06,37.06 81.89,38.23 76.94,38.23 75.95,39.22 75.95,43.96 76.81,44.83 93.45,44.83 95.23,46.61 99.21,46.61 99.69,46.12 99.69,35.28 97.56,33.15 91.97,33.15 90.04,31.22 90.04,9.76 87.91,7.62
AGND on TOP (solid shape): 93.85,159.64 92.93,159.64 92.42,160.15 92.93,160.66 93.85,160.66
AGND on TOP (solid shape): 93.85,155.96 92.93,155.96 92.42,156.46 92.93,156.97 93.85,156.97
AGND on TOP (solid shape): 93.85,153.16 92.93,153.16 92.42,153.67 92.93,154.18 93.85,154.18
AGND on TOP (solid shape): 101.47,129.64 100.97,129.13 100.46,129.64 100.46,130.56 101.47,130.56
AGND on TOP (solid shape): 104.9,129.64 104.39,129.13 103.89,129.64 103.89,130.56 104.9,130.56
AGND on TOP (solid shape): 110.11,129.63 109.6,129.13 109.09,129.63 109.09,130.55 110.11,130.55
AGND on TOP: 105.16,144.91 107.57,144.91 107.82,144.65 107.82,142.37 107.57,142.11 105.16,142.11 104.9,142.37 104.9,144.65
AGND on TOP: 92.96,172.09 92.96,161.29 93.09,161.16 93.6,161.16 93.73,161.04 93.73,152.78 93.6,152.65 93.09,152.65 92.96,152.53 92.96,149.61 93.34,149.22 101.35,149.22 101.85,149.73 101.85,151.13 102.11,151.38 106.05,151.38 106.68,152.02 106.68,156.97 107.57,157.86 113.03,157.86 113.67,158.5 113.67,171.45 113.03,172.09
AGND on BOTTOM: 96.27,129.54 95.38,130.43 95.38,148.72 95,149.1 93.22,149.1 92.84,149.48 92.84,172.21 113.41,172.21 113.67,171.96 113.67,129.92 113.28,129.54
AGND on L3_GND: 96.24,129.54 95.38,130.41 95.38,148.7 94.97,149.1 93.2,149.1 92.84,149.46 92.84,172.21 113.79,172.21 113.79,129.54
GND on TOP (solid shape): 92.17,160.15 92.68,159.64 91.31,159.64 91.31,160.66 92.67,160.66
GND on TOP (solid shape): 92.17,156.47 92.68,155.96 91.31,155.96 91.31,156.97 92.67,156.97
GND on TOP (solid shape): 92.17,153.67 92.68,153.16 91.31,153.16 91.31,154.18 92.67,154.18
GND on TOP (solid shape): 101.47,128.02 100.46,128.02 100.46,129.38 100.96,128.87 101.47,129.38
GND on TOP (solid shape): 104.9,128.02 103.89,128.02 103.89,129.38 104.39,128.87 104.9,129.38
GND on TOP (solid shape): 110.11,128.01 109.09,128.01 109.09,129.38 109.6,128.87 110.11,129.38
GND on TOP: 19.94,46.48 22.23,46.48 22.73,46.99 22.73,48.01 22.99,48.26 25.91,48.26 26.54,47.62 29.59,47.62 29.72,47.75 29.72,49.15 29.59,49.28 26.54,49.28 25.78,50.04 23.37,50.04 22.48,49.15 19.94,49.15 19.56,48.77 19.56,46.86
GND on TOP: 94.87,43.43 95.5,42.8 95.5,39.37 95.38,39.24 94.23,39.24 93.98,39.5 93.98,42.55 93.6,42.93 92.71,42.93 92.2,43.43 92.2,46.1 92.71,46.61 94.36,46.61 94.87,46.1
GND on TOP: outline of 140 points within 0.64,0.64 113.79,129.03
GND on TOP: 36.42,114.12 36.42,111.33 36.63,111.12 37.08,111.12 37.47,110.74 37.47,108.2 37.08,107.82 34.92,107.82 34.7,108.05 34.7,113.77 35.15,114.22 35.15,116.56 35.31,116.71 37.21,116.71 37.33,116.6 37.33,116.59 37.47,116.45 37.47,115.16
GND on TOP: outline of 100 points within 0.73,63.18 92.33,172.09 ; 1 cut-out
GND on TOP: 85.6,129.79 86.36,129.03 86.36,120.14 85.47,119.25 76.96,119.25 76.71,119.51 76.71,125.35 76.58,125.48 75.95,125.48 74.93,126.49 74.93,128.02 75.18,128.27 75.18,129.54 75.44,129.79
GND on TOP: 105.03,48.01 107.06,48.01 107.57,47.5 107.57,42.16 107.31,41.91 105.03,41.91 104.78,42.16 104.78,47.75
GND on BOTTOM: 81.69,47.17 81.81,47.17 100,65.35 100,76.48 102.03,78.51 103.63,78.51 104.29,77.85 104.29,54.41 100.57,50.69 100.57,48.55 96.93,44.91 96.93,36.47 98.48,34.92 98.48,20.65 97.66,19.84 85.52,19.84 81.38,23.98 81.38,28.17 80.87,28.68 79.48,28.68 78.11,30.05 78.11,34.44 77.6,34.95 75.62,34.95 74.96,35.61 74.96,40.44
GND on BOTTOM: 41.66,66.29 81.08,66.29 84.33,63.04 84.33,56.49 83.72,55.88 75.39,55.88 74.9,55.4 74.9,50.27 68.52,43.88 67.75,43.88 67.69,43.81 67.69,43.43 67.84,43.28 67.84,38.73 67.35,38.24 65.57,38.24 65.51,38.18 65.51,37.13 67.54,35.1 67.54,28.75 66.8,28.02 62.33,28.02 60.66,26.34 59.23,26.34 58.19,27.38 58.19,33.48 53.75,37.92 53.72,37.92 53.72,43.05 52.58,44.2 51.94,44.2 41.91,54.23 39.52,54.23 38.38,55.37 35.81,55.37 35.23,55.96 35.23,59.36 36.58,60.71 36.58,61.98 38.35,63.75 39.12,63.75
GND on BOTTOM: 75.69,129.69 85.88,129.69 87.1,128.47 87.1,115.7 93.68,109.12 93.68,88.09 92.43,86.84 92.43,64.62 90.25,62.43 88.77,62.43 87.73,63.47 87.73,81.94 89.07,83.27 89.07,90.97 86.13,93.9 86.13,106.27 77.37,115.04 77.37,116.54 73.46,120.45 73.46,121.41 75.11,123.06 75.11,129.11
GND on BOTTOM: outline of 97 points within 0.53,0.64 113.77,172.09
GND on L3_GND: 0.51,0.51 0.51,63.63 1.15,69.47 0.51,75.3 0.51,172.21 92.33,172.21 92.33,149.25 92.99,148.59 94.76,148.59 94.87,148.48 94.87,130.2 96.03,129.03 113.79,129.03 113.79,0.51
VDD on TOP (solid shape): 20.86,151.89 20.35,151.39 19.43,151.39 19.43,152.4 20.35,152.4
VDD on TOP: 71.12,57.15 70.87,57.4 70.87,60.33 73.15,62.61 104.14,62.61 111.25,55.5 111.25,37.47 110.74,36.96 108.58,36.96 107.95,37.59 107.95,50.16 104.78,53.34 102.23,53.34 101.85,53.72 101.85,58.8 99.95,60.71 85.6,60.71 82.04,57.15 78.11,57.15 78.11,58.8 75.06,58.8 75.06,57.15
VDD on L2_VCC: outline of 93 points within 0.51,13.72 113.79,172.21
VDD_ADJ on TOP: 96.39,40.64 100.58,40.64 101.73,39.5 106.93,39.5 107.31,39.12 107.31,37.47 106.55,36.7 102.23,36.7 101.66,36.13 99.5,36.13 98.68,35.31 95.5,35.31 95.12,35.69 95.12,37.85 95.63,38.35 95.63,38.99 95.89,39.24 95.89,40.13
VDD_ANA on TOP: 101.22,146.05 103.63,146.05 103.89,145.8 103.89,142.24 103.63,141.99 101.47,141.99 101.22,142.24 101.22,143.51 100.58,144.15 99.44,144.15 99.31,144.27 99.31,145.29 99.44,145.41 100.58,145.41
VDD_ANA on TOP: 99.06,129.67 96.01,129.67 95.76,129.92 95.76,131.44 98.93,134.62 98.93,136.27 99.31,136.65 99.31,137.79 99.44,137.92 100.2,137.92 100.46,138.18 100.46,138.68 100.84,139.06 101.35,139.06 101.47,138.94 101.47,132.72 99.31,130.56 99.31,129.92
VDD_ANA on L2_VCC: 95.38,129.54 95.38,148.7 94.97,149.1 93.2,149.1 92.84,149.46 92.84,172.21 113.79,172.21 113.79,129.54
VDD_MCU on L2_VCC: 48.49,112.78 42.14,119.13 36.05,119.13 35.05,120.12 35.05,126.39 39.37,130.7 39.37,131.95 40.62,131.95 41.27,132.61 41.27,140.48 44.05,143.26 66.65,143.26 75.92,152.53 92.33,152.53 92.33,149.25 92.99,148.59 94.76,148.59 94.87,148.48 94.87,124.06 92.99,122.17 82.7,122.17 73.3,112.78
CAL_D on TOP: 68.33,50.8 67.56,51.56 67.56,58.42 67.31,58.67 65.53,58.67 65.28,58.42 65.28,56.64 65.15,56.52 61.85,56.52 61.59,56.77 61.59,58.93 61.09,59.44 58.29,59.44 57.91,59.05 57.91,56.9 57.66,56.64 54.61,56.64 54.48,56.77 54.48,58.8 53.98,59.31 51.44,59.31 50.8,58.67 50.8,56.77 47.24,56.77 47.12,56.9 47.12,60.33 48.39,61.59 68.2,61.59 69.47,60.33 69.47,55.75 69.85,55.37 76.58,55.37 76.83,55.12 76.83,53.98 76.58,53.72 75.18,53.72 74.93,53.47 74.93,51.18 74.55,50.8
E5V on TOP: 21.21,39.88 21.21,35.56 19.43,33.78 5.59,33.78 4.95,33.15 3.3,33.15 2.16,34.29 2.16,37.47 3.3,38.61 12.83,38.61 15.11,40.89 20.19,40.89
LC_H on TOP (solid shape): 38.32,99.7 38.83,99.19 37.47,99.19 37.47,100.2 38.83,100.2
LC_L on TOP (solid shape): 38.32,98.3 38.83,97.79 37.47,97.79 37.47,98.81 38.83,98.81
LCDSEG0 on TOP (solid shape): 70.99,143.42 70.48,143.92 69.97,143.41 69.97,144.78 70.99,144.78
LCDSEG1 on TOP (solid shape): 65.66,143.42 65.15,143.92 64.64,143.41 64.64,144.78 65.66,144.78
LCDSEG4 on TOP (solid shape): 77.34,101.47 76.42,101.47 75.91,101.98 76.42,102.49 77.34,102.49
LCDSEG5 on TOP (solid shape): 60.83,139.86 60.83,138.94 59.82,138.94 59.82,139.86 60.33,140.37
LCDSEG5 on TOP (solid shape): 66.51,101.98 67.02,101.47 65.66,101.47 65.66,102.49 67.02,102.49
LCDSEG5 on TOP (solid shape): 75.66,101.98 76.17,101.47 74.8,101.47 74.8,102.49 76.16,102.49
LCDSEG6 on TOP (solid shape): 58.42,139.86 58.42,138.94 57.4,138.94 57.4,139.86 57.91,140.37
LCDSEG7 on TOP (solid shape): 57.05,114.68 56.55,114.17 55.63,114.17 55.63,115.19 56.55,115.19
